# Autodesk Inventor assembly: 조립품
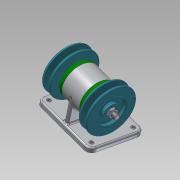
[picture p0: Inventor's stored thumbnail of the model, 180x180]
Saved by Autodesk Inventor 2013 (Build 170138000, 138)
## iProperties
Created: 2019-09
Part Number: 조립품
Document SubType Name: Assembly
Designer: Administrator
Author: Administrator
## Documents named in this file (10)
- C:\Users\Administrator\Desktop\490904V1038\조립품.iam
- C:\Users\Administrator\Desktop\490904V1038\축.ipt
- C:\Users\Administrator\Desktop\490904V1038\베어링 6004.ipt
- C:\Users\Administrator\Desktop\490904V1038\커버.ipt
- C:\Users\Administrator\Desktop\490904V1038\오일 실 17 30 5.ipt
- C:\Users\Administrator\Desktop\490904V1038\본체.ipt
- C:\Users\Administrator\Desktop\490904V1038\볼트 M4.ipt
- C:\Users\Administrator\Desktop\490904V1038\키 5 x 5 x 12.ipt
- C:\Users\Administrator\Desktop\490904V1038\V-벨트풀리.ipt
- C:\Users\Administrator\Desktop\490904V1038\너트 M10x1.ipt
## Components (2 placed, 1 different names)
1. V-벨트풀리:1
2. V-벨트풀리:2
